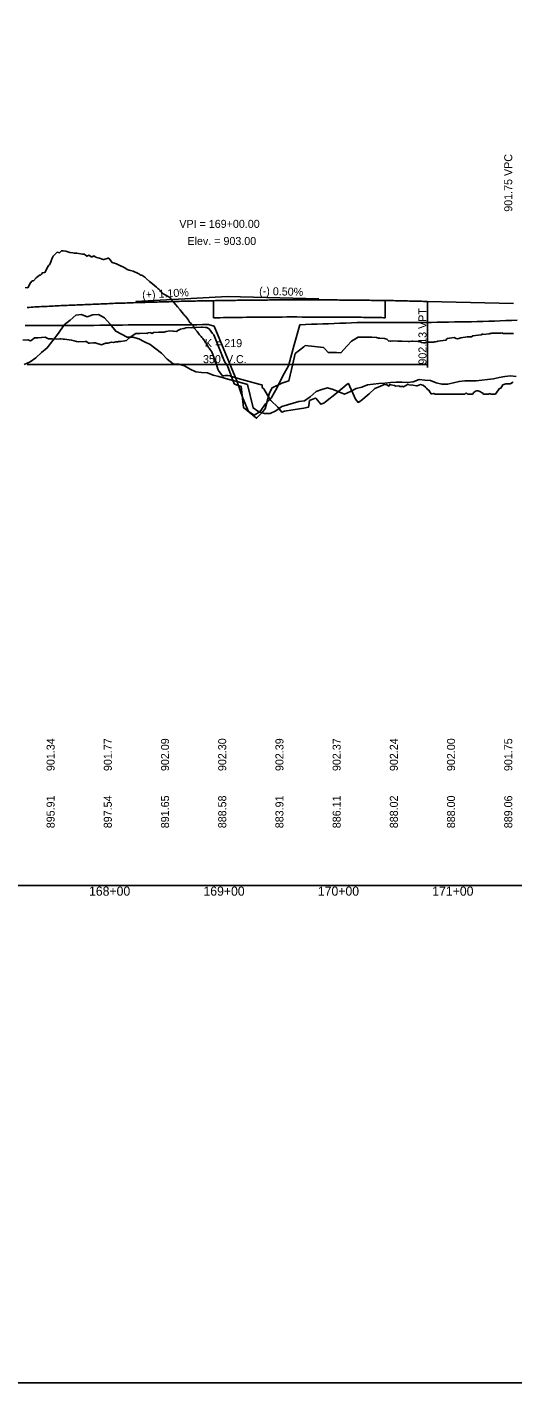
# Model space of a CAD drawing. Extents: x 1475774 to 1484571, y 1098511 to 1113011.
# Drawn here: x 1479496 to 1479921, y 1103076 to 1104262 of the extents above; entities that cross this region are included whole.
import ezdxf

# ---------------------------------------------------------------- set-up
doc = ezdxf.new("R2010")
doc.units = 0
for name, color, linetype in [('RD_DDB_GradeTX', 7, 'Continuous'), ('RD_DDB_PointTX', 7, 'Continuous'), ('RD_DDB_Profile_EX', 7, 'Continuous'), ('RD_DDB_Profile_Lbl', 7, 'Continuous'), ('RD_DDB_Profile_PR', 7, 'Continuous'), ('RD_DDB_StaTX', 7, 'Continuous'), ('RD_DDB_StripGrade', 7, 'Continuous'), ('RD_DDB_VCLbl', 7, 'Continuous'), ('RD_GPK_Profile_Cell', 7, 'Continuous'), ('RD_PD_Bridge', 7, 'Continuous'), ('RD_Sketch2', 7, 'Continuous'), ('RD_Sketch3', 7, 'Continuous'), ('RD_Sketch5', 7, 'Continuous')]:
    doc.layers.add(name, color=color, linetype=linetype)

msp = doc.modelspace()

# ---------------------------------------------------------------- linework, layer by layer
at = {"layer": 'RD_DDB_GradeTX'}
for p in [(1479591.1, 1104021.9), (1479751, 1104024.2)]:
    msp.add_line(p, (1479671, 1104026.2), dxfattribs=at)
at = {"layer": 'RD_DDB_PointTX'}
for points in [[(1479664.4, 1103988.2), (1479669.4, 1103976.2), (1479674.4, 1103964.3), (1479679.4, 1103952.3), (1479684.4, 1103937.3), (1479689.4, 1103925.5), (1479694.4, 1103922.3), (1479699.4, 1103925.4), (1479704.4, 1103932.4), (1479709.4, 1103937.4), (1479714.4, 1103946.5), (1479719.4, 1103956.7), (1479724.4, 1103965.6), (1479729.4, 1103983.9), (1479734.4, 1104001.5), (1479739.4, 1104001.7), (1479744.4, 1104001.9), (1479749.4, 1104002), (1479754.4, 1104002.2), (1479759.4, 1104002.4), (1479764.4, 1104002.6), (1479769.4, 1104002.8), (1479774.4, 1104002.9), (1479779.4, 1104003.1), (1479784.4, 1104003.3), (1479789.4, 1104003.4), (1479794.4, 1104003.3), (1479799.4, 1104003.3), (1479804.4, 1104003.3), (1479809.4, 1104003.3), (1479814.4, 1104003.3), (1479819.4, 1104003.3), (1479824.4, 1104003.3), (1479829.4, 1104003.3), (1479834.4, 1104003.3), (1479839.4, 1104003.3), (1479844.4, 1104003.4), (1479849.4, 1104003.5), (1479854.4, 1104003.6), (1479859.4, 1104003.7), (1479864.4, 1104003.8), (1479869.4, 1104003.9), (1479874.4, 1104003.9), (1479879.4, 1104004), (1479884.4, 1104004.1), (1479889.4, 1104004.3), (1479894.4, 1104004.4), (1479899.4, 1104004.6), (1479904.4, 1104004.7), (1479909.4, 1104004.9), (1479914.4, 1104005.1), (1479919.4, 1104005.2), (1479924.4, 1104005.4)], [(1479494.4, 1104000.8), (1479499.4, 1104000.7), (1479504.4, 1104000.7), (1479509.4, 1104000.7), (1479514.4, 1104000.7), (1479519.4, 1104000.7), (1479524.4, 1104000.7), (1479529.4, 1104000.7), (1479534.4, 1104000.7), (1479539.4, 1104000.7), (1479544.4, 1104000.8), (1479549.4, 1104000.9), (1479554.4, 1104000.9), (1479559.4, 1104001), (1479564.4, 1104001), (1479569.4, 1104001.1), (1479574.4, 1104001.2), (1479579.4, 1104001.2), (1479584.4, 1104001.3), (1479589.4, 1104001.3), (1479594.4, 1104001.3), (1479599.4, 1104001.3), (1479604.4, 1104001.3), (1479609.4, 1104001.4), (1479614.4, 1104001.4), (1479619.4, 1104001.4), (1479624.4, 1104001.4), (1479629.4, 1104001.4), (1479634.4, 1104001.5), (1479639.4, 1104001.5), (1479644.4, 1104001.5), (1479649.4, 1104001.6), (1479654.4, 1104001.6), (1479659.4, 1104000.1), (1479664.4, 1103988.2)]]:
    msp.add_lwpolyline(points, dxfattribs=at)
at = {"layer": 'RD_DDB_Profile_EX'}
for points in [[(1479493.5, 1103966.7), (1479498.5, 1103968.9), (1479503.5, 1103972.4), (1479508.5, 1103977.1), (1479513.5, 1103981.2), (1479518.5, 1103987.6), (1479523.5, 1103994.1), (1479528.5, 1104001.3), (1479533.5, 1104005.5), (1479538.5, 1104009.8), (1479543.5, 1104010.3), (1479548.5, 1104008.4), (1479553.5, 1104010), (1479558.5, 1104010.4), (1479563.5, 1104007.4), (1479568.5, 1104002), (1479573.5, 1103995.8), (1479578.5, 1103993.3), (1479583.5, 1103990.5), (1479588.5, 1103990.5), (1479593.5, 1103989.1), (1479598.5, 1103986.5), (1479603.5, 1103984.2), (1479608.5, 1103980.4), (1479613.5, 1103976.7), (1479618.5, 1103971.5), (1479623.5, 1103967.4), (1479628.5, 1103967.1), (1479633.5, 1103965.5), (1479638.5, 1103962.7), (1479643.5, 1103960.4), (1479648.5, 1103959.6), (1479653.5, 1103959.5), (1479658.5, 1103957.5), (1479663.5, 1103956.1)], [(1479663.5, 1103956.1), (1479668.5, 1103954.9), (1479673.5, 1103953.4), (1479678.5, 1103952), (1479683.5, 1103950.6), (1479688.5, 1103949.1), (1479693.5, 1103928.7), (1479698.5, 1103925.3), (1479703.5, 1103924), (1479708.5, 1103923.9), (1479713.5, 1103926.3), (1479718.5, 1103930.1), (1479723.5, 1103931.5), (1479728.5, 1103932.9), (1479733.5, 1103934.3), (1479738.5, 1103935), (1479743.5, 1103938.4), (1479748.5, 1103943.1), (1479753.5, 1103944.8), (1479758.5, 1103946.4), (1479763.5, 1103944.9), (1479768.5, 1103942.8), (1479773.5, 1103940.7), (1479778.5, 1103943.1), (1479783.5, 1103945.6), (1479788.5, 1103946.9), (1479793.5, 1103948.8), (1479798.5, 1103949.4), (1479803.5, 1103950), (1479808.5, 1103950.3), (1479813.5, 1103950.9), (1479818.5, 1103951.4), (1479823.5, 1103951.3), (1479828.5, 1103951), (1479833.5, 1103951.6), (1479838.5, 1103953.5), (1479843.5, 1103953.1), (1479848.5, 1103952.6), (1479853.5, 1103950.6), (1479858.5, 1103949.5), (1479863.5, 1103949.5), (1479868.5, 1103950.6), (1479873.5, 1103951.9), (1479878.5, 1103952.4), (1479883.5, 1103952.3), (1479888.5, 1103952.4), (1479893.5, 1103952.9), (1479898.5, 1103953.5), (1479903.5, 1103954.3), (1479908.5, 1103955.2), (1479913.5, 1103956.2), (1479918.5, 1103956.7), (1479923.5, 1103956.3)]]:
    msp.add_lwpolyline(points, dxfattribs=at)
at = {"layer": 'RD_DDB_Profile_PR'}
msp.add_line((1479846, 1104021.9), (1479921, 1104020), dxfattribs=at)
msp.add_line((1479846, 1104021.9), (1479921, 1104020), dxfattribs=at)
msp.add_spline([(1479496, 1104016.6), (1479503, 1104017), (1479510, 1104017.4), (1479517, 1104017.7), (1479524, 1104018.1), (1479531, 1104018.4), (1479538, 1104018.7), (1479545, 1104019), (1479552, 1104019.3), (1479559, 1104019.6), (1479566, 1104019.9), (1479573, 1104020.2), (1479580, 1104020.4), (1479587, 1104020.7), (1479594, 1104020.9), (1479601, 1104021.1), (1479608, 1104021.3), (1479615, 1104021.5), (1479622, 1104021.7), (1479629, 1104021.9), (1479636, 1104022.1), (1479643, 1104022.2), (1479650, 1104022.4), (1479657, 1104022.5), (1479664, 1104022.6), (1479671, 1104022.7), (1479678, 1104022.8), (1479685, 1104022.9), (1479692, 1104023), (1479699, 1104023.1), (1479706, 1104023.1), (1479713, 1104023.2), (1479720, 1104023.2), (1479727, 1104023.2), (1479734, 1104023.2), (1479741, 1104023.2), (1479748, 1104023.2), (1479755, 1104023.2), (1479762, 1104023.2), (1479769, 1104023.1), (1479776, 1104023.1), (1479783, 1104023), (1479790, 1104022.9), (1479797, 1104022.8), (1479804, 1104022.7), (1479811, 1104022.6), (1479818, 1104022.5), (1479825, 1104022.3), (1479832, 1104022.2), (1479839, 1104022), (1479846, 1104021.9)], degree=3, dxfattribs=at)
msp.add_spline([(1479496, 1104016.6), (1479503, 1104017), (1479510, 1104017.4), (1479517, 1104017.7), (1479524, 1104018.1), (1479531, 1104018.4), (1479538, 1104018.7), (1479545, 1104019), (1479552, 1104019.3), (1479559, 1104019.6), (1479566, 1104019.9), (1479573, 1104020.2), (1479580, 1104020.4), (1479587, 1104020.7), (1479594, 1104020.9), (1479601, 1104021.1), (1479608, 1104021.3), (1479615, 1104021.5), (1479622, 1104021.7), (1479629, 1104021.9), (1479636, 1104022.1), (1479643, 1104022.2), (1479650, 1104022.4), (1479657, 1104022.5), (1479664, 1104022.6), (1479671, 1104022.7), (1479678, 1104022.8), (1479685, 1104022.9), (1479692, 1104023), (1479699, 1104023.1), (1479706, 1104023.1), (1479713, 1104023.2), (1479720, 1104023.2), (1479727, 1104023.2), (1479734, 1104023.2), (1479741, 1104023.2), (1479748, 1104023.2), (1479755, 1104023.2), (1479762, 1104023.2), (1479769, 1104023.1), (1479776, 1104023.1), (1479783, 1104023), (1479790, 1104022.9), (1479797, 1104022.8), (1479804, 1104022.7), (1479811, 1104022.6), (1479818, 1104022.5), (1479825, 1104022.3), (1479832, 1104022.2), (1479839, 1104022), (1479846, 1104021.9)], degree=3, dxfattribs=at)
at = {"layer": 'RD_DDB_VCLbl'}
for p, q in [((1479846, 1103964.1), (1479846, 1104021.9)), ((1479496, 1103966.6), (1479846, 1103966.6))]:
    msp.add_line(p, q, dxfattribs=at)
at = {"layer": 'RD_GPK_Profile_Cell'}
msp.add_line((1477571, 1103511.2), (1484571, 1103511.2), dxfattribs=at)
at = {"layer": 'RD_PD_Bridge'}
for p, q in [((1479659, 1104022.6), (1479659, 1104007.5)), ((1479809, 1104007.6), (1479809, 1104022.6))]:
    msp.add_line(p, q, dxfattribs=at)
msp.add_open_spline([(1479659, 1104007.5), (1479663.1, 1104007.6), (1479667.1, 1104007.7), (1479700.2, 1104008.2), (1479729.3, 1104008.3), (1479772.9, 1104008.1), (1479787.5, 1104008), (1479804.3, 1104007.7), (1479806.7, 1104007.7), (1479809, 1104007.6)], degree=3, dxfattribs=at)
at = {"layer": 'RD_Sketch2'}
msp.add_lwpolyline([(1479492.3, 1103988.1), (1479496.7, 1103988.4), (1479498.9, 1103987.5), (1479500.3, 1103988.2), (1479502.5, 1103989.9), (1479505.7, 1103990.1), (1479508.4, 1103990.3), (1479511.7, 1103990.6), (1479514.7, 1103989.3), (1479515.7, 1103989.1), (1479516.9, 1103989.1), (1479518, 1103989.1), (1479521.5, 1103989), (1479524.7, 1103989.2), (1479525.5, 1103989.1), (1479527.6, 1103989), (1479528.7, 1103989), (1479534.9, 1103988.1), (1479537.1, 1103987.5), (1479539.1, 1103986.9), (1479541.2, 1103986.6), (1479546.7, 1103986.8), (1479547.9, 1103986.9), (1479549.6, 1103985.5), (1479550.5, 1103985.4), (1479554, 1103985.8), (1479555.4, 1103985.7), (1479556.2, 1103985.4), (1479561.1, 1103983.9), (1479564.4, 1103985.4), (1479565.8, 1103985.3), (1479566.6, 1103985.3), (1479569.6, 1103986.1), (1479571.6, 1103985.9), (1479573.4, 1103986.4), (1479575.4, 1103986.6), (1479575.9, 1103986.7), (1479577.5, 1103986.9), (1479581.3, 1103987.4), (1479582.8, 1103987.8), (1479585, 1103989.8), (1479590.5, 1103993.6), (1479591.1, 1103993.8), (1479591.9, 1103993.8), (1479594.5, 1103993.9), (1479600, 1103994.2), (1479601.1, 1103993.7), (1479601.6, 1103994.4), (1479603.7, 1103994.6), (1479604.1, 1103994.5), (1479605.2, 1103993.9), (1479606.4, 1103994.6), (1479611.1, 1103994.9), (1479613.7, 1103995.1), (1479615.7, 1103994.9), (1479617.5, 1103995.7), (1479620.7, 1103996.2), (1479623.2, 1103995.9), (1479623.9, 1103995.8), (1479626.3, 1103995.5), (1479628.8, 1103997.1), (1479630.1, 1103997.5), (1479632.7, 1103998.1), (1479633.3, 1103998.2), (1479634.7, 1103998.8), (1479637.4, 1103999.1), (1479639.7, 1103998.9), (1479641.9, 1103999), (1479642.3, 1103999), (1479643.5, 1103999), (1479648.2, 1103999.3), (1479649, 1103999.3), (1479651.9, 1103999.2), (1479653.1, 1103999.2), (1479654.5, 1103998.3), (1479655, 1103997.8), (1479658, 1103993.9), (1479659.1, 1103992.8), (1479661.4, 1103986.9), (1479668.5, 1103969.3), (1479671, 1103965.5), (1479676.9, 1103949.9), (1479678.1, 1103949.2), (1479680.5, 1103948.4), (1479683, 1103947.6), (1479685.1, 1103929), (1479690, 1103925), (1479696.5, 1103919.7), (1479699.6, 1103923), (1479701.9, 1103925.6), (1479703.9, 1103927.9), (1479707.4, 1103941.1), (1479709.1, 1103944.3), (1479710.2, 1103946.4), (1479718.6, 1103950.3), (1479719.5, 1103950.7), (1479724.6, 1103952.3), (1479728.2, 1103967.2), (1479730.3, 1103976.3), (1479737.7, 1103982.1), (1479739.1, 1103983.2), (1479747.2, 1103982.4), (1479754.9, 1103981.7), (1479756.7, 1103979.7), (1479759.2, 1103977.2), (1479766.3, 1103977.1), (1479770.3, 1103977), (1479775.8, 1103983), (1479779.6, 1103987.1), (1479785.3, 1103990.7), (1479787.2, 1103990.7), (1479792.3, 1103990.5), (1479794.3, 1103990.7), (1479794.9, 1103990.7), (1479795.6, 1103990.6), (1479797.4, 1103990.5), (1479801.2, 1103990.4), (1479803.1, 1103989.7), (1479804.4, 1103989.6), (1479808.3, 1103989.4), (1479810.5, 1103989), (1479811.7, 1103987.3), (1479813.3, 1103987), (1479813.9, 1103987.1), (1479815.5, 1103987.3), (1479819.9, 1103987), (1479820.9, 1103987.2), (1479822.3, 1103987.1), (1479823.4, 1103987.1), (1479828.9, 1103986.8), (1479830.3, 1103986.7), (1479832.2, 1103987), (1479833, 1103987), (1479837.5, 1103986.8), (1479839.4, 1103986.7), (1479840.7, 1103985.9), (1479842.5, 1103985.8), (1479843.9, 1103985.7), (1479845.9, 1103986.1), (1479851.3, 1103986.3), (1479852, 1103986.4), (1479852.7, 1103986.5), (1479854.3, 1103986.8), (1479854.9, 1103987.2), (1479862, 1103987.9), (1479863.2, 1103989.4), (1479869.2, 1103990.2), (1479871.1, 1103989.5), (1479872, 1103989.1), (1479873.3, 1103989.4), (1479875, 1103990), (1479880.6, 1103990.9), (1479881.4, 1103991), (1479882.3, 1103990.8), (1479883.3, 1103990.9), (1479884.3, 1103990.9), (1479885.4, 1103991.8), (1479890.1, 1103992.4), (1479892.8, 1103992.8), (1479893.9, 1103993.4), (1479894.4, 1103992.9), (1479899.7, 1103993.6), (1479900.4, 1103993.7), (1479901.2, 1103993.8), (1479902.2, 1103994.1), (1479909.2, 1103994.2), (1479910, 1103994.2), (1479910.8, 1103994.3), (1479911.4, 1103994.2), (1479912.1, 1103993.7), (1479918.7, 1103993.9), (1479920.5, 1103993.9), (1479921.1, 1103993.8)], dxfattribs=at)
at = {"layer": 'RD_Sketch3'}
msp.add_lwpolyline([(1479494.4, 1104034), (1479496.5, 1104033.7), (1479498.9, 1104038.1), (1479500.2, 1104039.5), (1479500.8, 1104039.8), (1479501.6, 1104039.9), (1479503.9, 1104042.4), (1479506.7, 1104044.9), (1479507.6, 1104044.8), (1479508.4, 1104045.8), (1479509.4, 1104047), (1479511.5, 1104047.3), (1479511.9, 1104047.9), (1479513.7, 1104051.9), (1479515, 1104053.5), (1479515.8, 1104054.2), (1479517, 1104057.3), (1479518, 1104059.8), (1479518.6, 1104061.5), (1479522.3, 1104064.9), (1479524.4, 1104064.4), (1479526, 1104066.1), (1479527.6, 1104066.1), (1479529.7, 1104065.8), (1479532.4, 1104065), (1479533.4, 1104064.7), (1479535.9, 1104064.3), (1479537.1, 1104064.2), (1479537.5, 1104064.2), (1479539.4, 1104064.2), (1479540.8, 1104063.8), (1479542.7, 1104063.4), (1479544.5, 1104063.3), (1479545.9, 1104063.3), (1479546.7, 1104062.5), (1479548.2, 1104061.4), (1479550.1, 1104062.2), (1479551.9, 1104061), (1479552.9, 1104061), (1479554.4, 1104061.6), (1479555.5, 1104061), (1479556.2, 1104060.6), (1479556.6, 1104060.4), (1479558, 1104059.9), (1479559.2, 1104059.6), (1479562.4, 1104058.6), (1479563.1, 1104058.5), (1479565.8, 1104059.4), (1479566.6, 1104059.7), (1479567.3, 1104059.7), (1479568.2, 1104058.5), (1479570.3, 1104055.9), (1479573.3, 1104055), (1479574, 1104054.8), (1479575.4, 1104054.2), (1479575.8, 1104054), (1479577.7, 1104053), (1479578, 1104052.8), (1479578.4, 1104052.7), (1479581.4, 1104051.1), (1479583.5, 1104049.8), (1479585.1, 1104049.1), (1479588.8, 1104048.3), (1479589.3, 1104048.1), (1479592.5, 1104046.5), (1479593, 1104046.4), (1479593.7, 1104046), (1479594.5, 1104045.4), (1479595.2, 1104044.7), (1479596.2, 1104044.8), (1479598.8, 1104043), (1479599.9, 1104042), (1479602.9, 1104039.4), (1479604.1, 1104038.3), (1479607.3, 1104035.7), (1479609, 1104034.3), (1479610.2, 1104033.1), (1479611.1, 1104032.7), (1479612.3, 1104031.5), (1479613.6, 1104029.8), (1479614.1, 1104029.2), (1479614.8, 1104028.6), (1479616.6, 1104027.6), (1479618.8, 1104026.6), (1479619.2, 1104026.3), (1479620.9, 1104025.1), (1479622.2, 1104023.4), (1479623.2, 1104022.2), (1479624.2, 1104021), (1479625.9, 1104018.9), (1479627.3, 1104017.1), (1479629.6, 1104014.6), (1479630.4, 1104013.6), (1479632.7, 1104010.8), (1479633.3, 1104010.1), (1479633.8, 1104009.4), (1479634.4, 1104009), (1479637, 1104005.5), (1479638, 1104003.7), (1479639.4, 1104002.6), (1479640.7, 1104001.2), (1479642.3, 1103998.2), (1479644.5, 1103995.6), (1479646.6, 1103992.6), (1479648.2, 1103991.1), (1479648.8, 1103990.2), (1479649.6, 1103989.5), (1479650.9, 1103987.5), (1479651.9, 1103985.7), (1479653, 1103984.5), (1479654.6, 1103981.6), (1479655.2, 1103980.9), (1479655.6, 1103980), (1479657.3, 1103977.8), (1479659.5, 1103972.3), (1479660.4, 1103969.4), (1479661.4, 1103966.8), (1479662.8, 1103962.7), (1479663.3, 1103961.4), (1479664.7, 1103959.5), (1479665.8, 1103958.1), (1479666.5, 1103957.2), (1479667, 1103956.9), (1479667.8, 1103956.9), (1479669.2, 1103957.1), (1479670.1, 1103957.1), (1479671, 1103957.1), (1479671.5, 1103957), (1479673.1, 1103956.9), (1479673.5, 1103956.5), (1479675.8, 1103955.9), (1479680.5, 1103954.6), (1479690, 1103951.9), (1479699.6, 1103949.3), (1479701.4, 1103948.8), (1479701.5, 1103946.5), (1479702.8, 1103945.5), (1479708.1, 1103936.3), (1479709.1, 1103935.3), (1479715, 1103929.3), (1479718.7, 1103925), (1479720.9, 1103925.9), (1479728.2, 1103927.1), (1479737.7, 1103928.6), (1479741.8, 1103929.3), (1479742.3, 1103930.8), (1479742.9, 1103935.1), (1479747.2, 1103937), (1479748.2, 1103937.4), (1479752.6, 1103932), (1479755.3, 1103932.8), (1479756.7, 1103934), (1479766.3, 1103941.7), (1479775.8, 1103949.4), (1479776.8, 1103950.2), (1479783, 1103936.3), (1479785.3, 1103933.6), (1479787.7, 1103934.8), (1479794.9, 1103941.1), (1479800, 1103945.7), (1479804.4, 1103947.6), (1479807.4, 1103948.9), (1479809.7, 1103949.2), (1479812.4, 1103947.9), (1479812.7, 1103949.1), (1479813, 1103949.1), (1479813.9, 1103948.9), (1479817.1, 1103948.4), (1479817.7, 1103948.2), (1479818.1, 1103947.9), (1479820.9, 1103948.2), (1479821.8, 1103947.5), (1479823.4, 1103947.6), (1479824.1, 1103947.7), (1479824.8, 1103947.2), (1479829, 1103949.4), (1479829.7, 1103949), (1479833, 1103948.7), (1479836.3, 1103948.2), (1479836.9, 1103948), (1479839.9, 1103949.2), (1479841.9, 1103948.7), (1479842.5, 1103948.3), (1479844.1, 1103946.9), (1479845, 1103945.9), (1479846, 1103944.9), (1479847.1, 1103944.2), (1479847.9, 1103942.8), (1479849.1, 1103941.2), (1479849.9, 1103941), (1479851.4, 1103941.4), (1479851.7, 1103941.3), (1479852, 1103941.1), (1479852.7, 1103940.8), (1479854.9, 1103940.8), (1479856.7, 1103940.8), (1479858.3, 1103940.8), (1479860, 1103940.8), (1479860.9, 1103940.8), (1479861.2, 1103940.8), (1479861.5, 1103940.8), (1479862.1, 1103940.8), (1479864.8, 1103940.8), (1479865.5, 1103940.8), (1479866.1, 1103940.8), (1479867.1, 1103940.8), (1479867.6, 1103940.8), (1479868.6, 1103940.8), (1479870.3, 1103940.8), (1479871.1, 1103940.8), (1479872.6, 1103940.8), (1479874.4, 1103940.8), (1479874.8, 1103940.8), (1479876, 1103940.8), (1479877.1, 1103940.8), (1479878.6, 1103940.8), (1479879.8, 1103941.9), (1479880.6, 1103941.2), (1479881.4, 1103940.8), (1479884.9, 1103940.8), (1479885.3, 1103940.8), (1479886.5, 1103942.2), (1479888, 1103943.5), (1479889, 1103943.7), (1479890.1, 1103943.7), (1479891.7, 1103943.1), (1479893.6, 1103941.8), (1479894, 1103941.8), (1479894.8, 1103940.8), (1479895.6, 1103940.8), (1479896.7, 1103940.8), (1479898.7, 1103940.8), (1479899.5, 1103940.8), (1479899.9, 1103941.3), (1479901.5, 1103940.8), (1479902.3, 1103940.8), (1479903.5, 1103940.8), (1479904.5, 1103940.8), (1479905.3, 1103940.8), (1479905.7, 1103941.4), (1479906, 1103941.7), (1479908.5, 1103945.3), (1479909.2, 1103945.6), (1479909.9, 1103946), (1479911.7, 1103949), (1479914.3, 1103949.7), (1479916.7, 1103949.9), (1479917.4, 1103949.8), (1479918.2, 1103949.9), (1479918.7, 1103950.2), (1479920.2, 1103951.1), (1479920.8, 1103951.5)], dxfattribs=at)
at = {"layer": 'RD_Sketch5'}
msp.add_lwpolyline([(1477722.7, 1103076.2), (1481322.7, 1103076.2), (1481322.7, 1105276.2), (1477722.7, 1105276.2)], close=True, dxfattribs=at)

# ---------------------------------------------------------------- texts
at = {"layer": 'RD_DDB_GradeTX'}
for s, rotation, p in [('(+) 1.10%', 3.1481, (1479596.7, 1104024.2)), ('(-) 0.50%', 358.5679, (1479698.7, 1104027.6))]:
    msp.add_text(s, height=7, rotation=rotation, dxfattribs=at).set_placement(p)
at = {"layer": 'RD_DDB_Profile_Lbl'}
for s, p in [('VPI = 169+00.00', (1479629, 1104086.2)), ('Elev. = 903.00', (1479636.1, 1104071.2))]:
    msp.add_text(s, height=7, dxfattribs=at).set_placement(p)
at = {"layer": 'RD_DDB_StaTX'}
for s, p in [('168+00', (1479550.1, 1103502.2)), ('169+00', (1479650.1, 1103502.2)), ('170+00', (1479750.1, 1103502.2)), ('171+00', (1479850.1, 1103502.2))]:
    msp.add_text(s, height=8, dxfattribs=at).set_placement(p)
at = {"layer": 'RD_DDB_StripGrade'}
for s, p in [('901.75 VPC', (1479920, 1104100.3)), ('902.13 VPT', (1479845, 1103966.6)), ('901.34', (1479520, 1103611.2)), ('901.77', (1479570, 1103611.2)), ('902.09', (1479620, 1103611.2)), ('902.30', (1479670, 1103611.2)), ('902.39', (1479720, 1103611.2)), ('902.37', (1479770, 1103611.2)), ('902.24', (1479820, 1103611.2)), ('902.00', (1479870, 1103611.2)), ('901.75', (1479920, 1103611.2)), ('895.91', (1479520, 1103561.2)), ('897.54', (1479570, 1103561.2)), ('891.65', (1479620, 1103561.2)), ('888.58', (1479670, 1103561.2)), ('883.91', (1479720, 1103561.2)), ('886.11', (1479770, 1103561.2)), ('888.02', (1479820, 1103561.2)), ('888.00', (1479870, 1103561.2)), ('889.06', (1479920, 1103561.2))]:
    msp.add_text(s, height=7, rotation=90, dxfattribs=at).set_placement(p)
at = {"layer": 'RD_DDB_VCLbl'}
for s, p in [('K = 219', (1479651.4, 1103981.9)), ("350' V.C.", (1479649.7, 1103967.9))]:
    msp.add_text(s, height=7, dxfattribs=at).set_placement(p)

doc.saveas('drawing.dxf')
